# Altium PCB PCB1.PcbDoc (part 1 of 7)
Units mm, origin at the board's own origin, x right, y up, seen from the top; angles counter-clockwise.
Board outline 139.9 x 46.81 mm, 2 copper layers (Top Layer, Bottom Layer); 0 components, 100 nets, 100 pads, 0 vias.
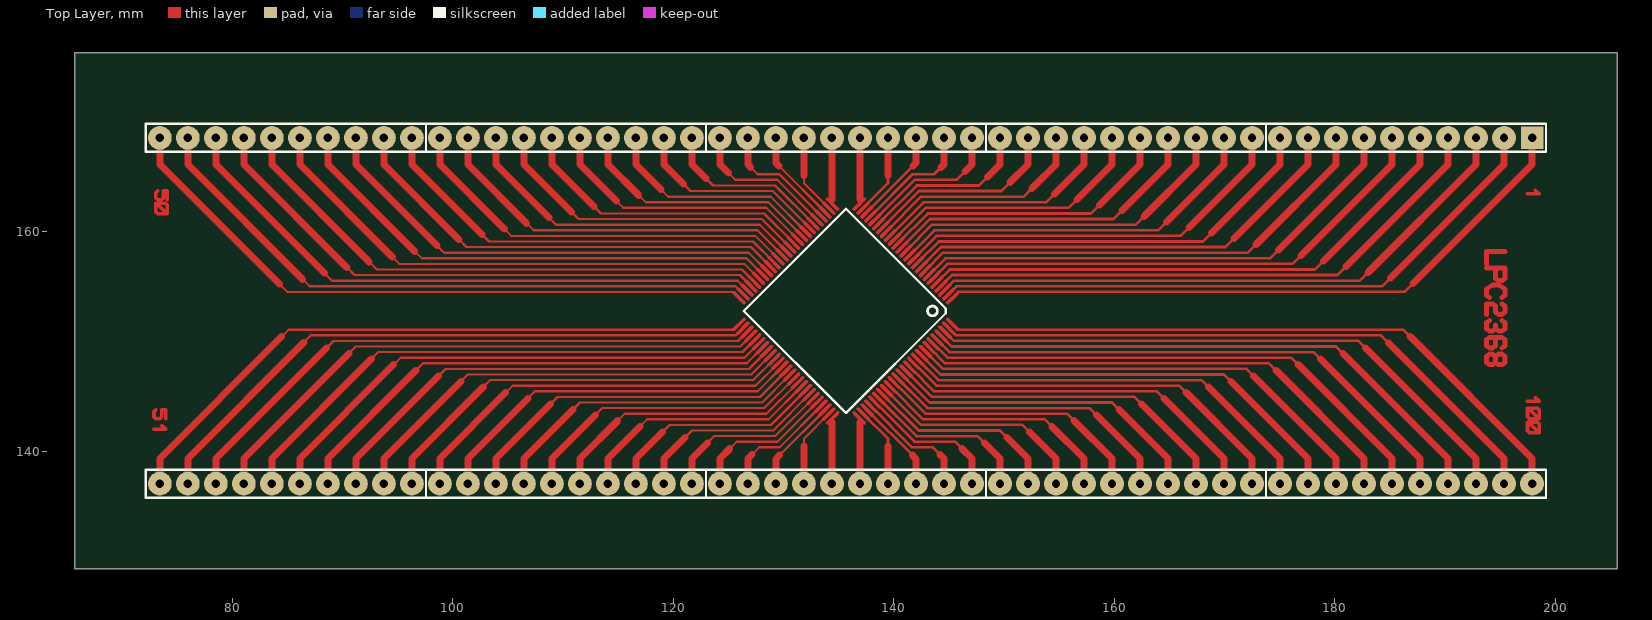
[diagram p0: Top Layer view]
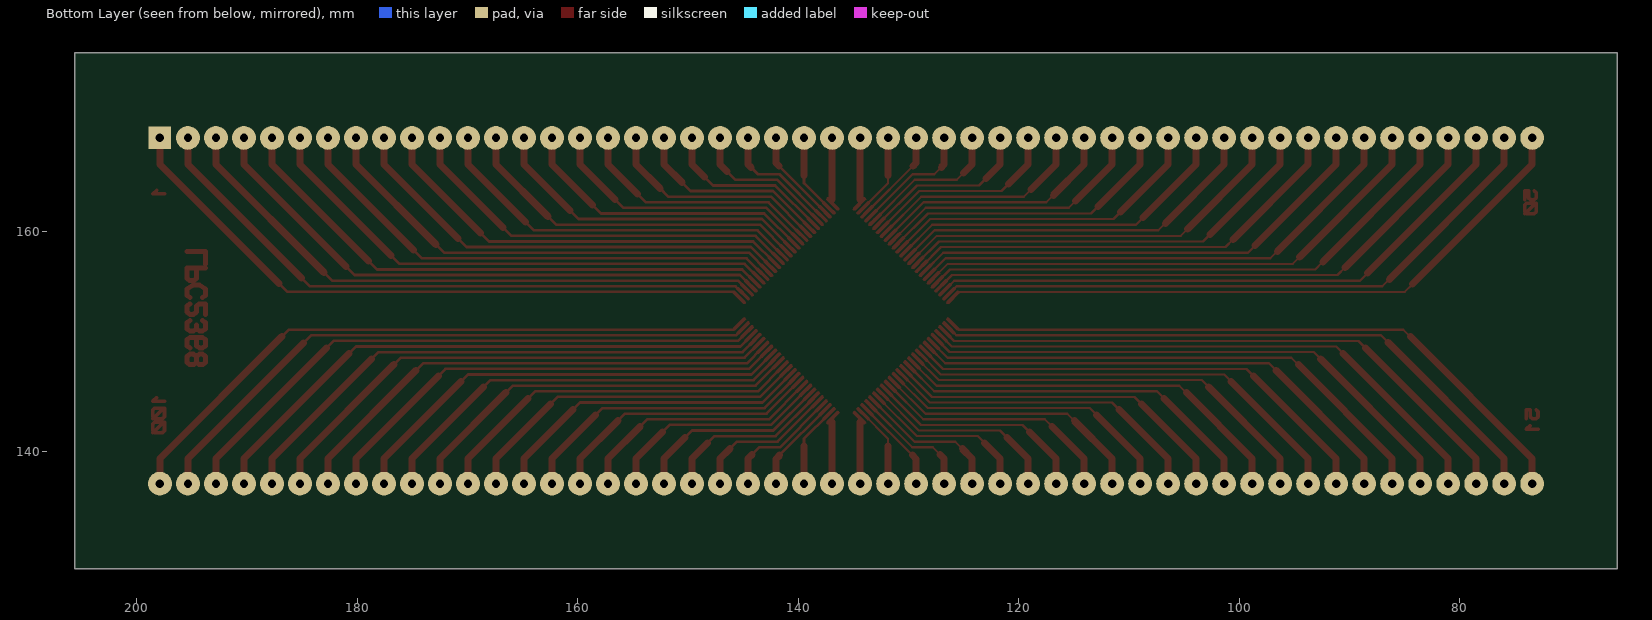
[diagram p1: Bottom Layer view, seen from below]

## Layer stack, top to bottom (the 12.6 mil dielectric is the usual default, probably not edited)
Top Layer: signal copper 0.0356
Dielectric: dielectric 0.32, FR-4, Dk 4.8
Bottom Layer: signal copper 0.0356

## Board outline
65.71,129.362 205.613,129.362 205.613,176.174 65.71,176.174

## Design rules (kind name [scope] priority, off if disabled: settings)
Clearance CAM_Clearance_2 [OnLayer('Top Layer')] p1: gap=0
Clearance CAM_Clearance_1 [OnLayer('Bottom Layer')] p2: gap=0.127
Clearance [All] p3: gap=0.254
PolygonConnect [All] p1: connectstyle=Relief reliefconductorwidth=0.254 reliefentries=4 polygonreliefangle="90 Angle"
RoutingVias [All] p1: holewidth=0.711 width=1.27 viastyle="Through Hole" minholewidth=0.711 minwidth=1.27 maxholewidth=0.711 maxwidth=1.27
SilkscreenOverComponentPads [All] p1: minsilkscreentomaskgap=0.254
SolderMaskExpansion [All] p1: expansion=0.102
Width CAM_Width_1 [OnLayer('Top Layer')] p1: maxlimit=0.66 minlimit=0.005 preferedwidth=0.03
Width [All] p2: maxlimit=0.254 minlimit=0.254 preferedwidth=0.254
27 further rules are at their usual default settings.

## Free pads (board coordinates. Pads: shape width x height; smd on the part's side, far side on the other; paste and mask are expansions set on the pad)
  round 2.159 hole 0.762: 1(73.427,137.086) 1(73.427,168.455) 1(75.967,137.086) 1(75.967,168.455) 1(78.507,137.086) 1(78.507,168.455) 1(81.047,137.086) 1(81.047,168.455) 1(83.587,137.086) 1(83.587,168.455) 1(86.127,137.086) 1(86.127,168.455) 1(88.667,137.086) 1(88.667,168.455) 1(91.207,137.086) 1(91.207,168.455) 1(93.747,137.086) 1(93.747,168.455) 1(96.287,137.086) 1(96.287,168.455) 1(98.827,137.086) 1(98.827,168.455) 1(101.367,137.086) 1(101.367,168.455) 1(103.907,137.086) 1(103.907,168.455) 1(106.447,137.086) 1(106.447,168.455) 1(108.987,137.086) 1(108.987,168.455) 1(111.527,137.086) 1(111.527,168.455) 1(114.067,137.086) 1(114.067,168.455) 1(116.607,137.086) 1(116.607,168.455) 1(119.147,137.086) 1(119.147,168.455) 1(121.687,137.086) 1(121.687,168.455) 1(124.227,137.086) 1(124.227,168.455) 1(126.767,137.086) 1(126.767,168.455) 1(129.307,137.086) 1(129.307,168.455) 1(131.847,137.086) 1(131.847,168.455) 1(134.387,137.086) 1(134.387,168.455) 1(136.927,137.086) 1(136.927,168.455) 1(139.467,137.086) 1(139.467,168.455) 1(142.007,137.086) 1(142.007,168.455) 1(144.547,137.086) 1(144.547,168.455) 1(147.087,137.086) 1(147.087,168.455) 1(149.627,137.086) 1(149.627,168.455) 1(152.167,137.086) 1(152.167,168.455) 1(154.707,137.086) 1(154.707,168.455) 1(157.247,137.086) 1(157.247,168.455) 1(159.787,137.086) 1(159.787,168.455) 1(162.327,137.086) 1(162.327,168.455) 1(164.867,137.086) 1(164.867,168.455) 1(167.407,137.086) 1(167.407,168.455) 1(169.947,137.086) 1(169.947,168.455) 1(172.487,137.086) 1(172.487,168.455) 1(175.025,137.086) 1(175.025,168.455) 1(177.565,137.086) 1(177.565,168.455) 1(180.105,137.086) 1(180.105,168.455) 1(182.645,137.086) 1(182.645,168.455) 1(185.185,137.086) 1(185.185,168.455) 1(187.725,137.086) 1(187.725,168.455) 1(190.265,137.086) 1(190.265,168.455) 1(192.805,137.086) 1(192.805,168.455) 1(195.345,137.086) 1(195.345,168.455) 1(197.885,137.086)
  rect 2.032x2.032 hole 0.762: 1(197.885,168.455)

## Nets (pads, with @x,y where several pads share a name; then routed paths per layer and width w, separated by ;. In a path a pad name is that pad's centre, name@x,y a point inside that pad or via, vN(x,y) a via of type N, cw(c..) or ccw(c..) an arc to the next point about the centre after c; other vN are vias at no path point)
$Net0: pad.1@73.427,168.455 | length 83.9
  Top Layer w0.03: 125.403,154.411 125.672,154.411 ; 125.406,154.396 125.688,154.396 ; 125.408,154.381 125.703,154.381 ; 125.416,154.365 125.718,154.365 ; 125.418,154.457 125.627,154.457 ; 125.429,154.35 125.733,154.35 ; 125.444,154.335 125.749,154.335 ; 125.444,154.487 125.596,154.487 ; 125.459,154.32 125.764,154.32 ; 125.462,154.503 125.581,154.503 ; 125.474,154.304 125.779,154.304 ; 125.484,154.518 125.558,154.518 ; 125.489,154.289 125.794,154.289 ; 125.505,154.274 125.81,154.274 ; 125.52,154.259 125.825,154.259 ; 125.535,154.243 125.84,154.243 ; 125.55,154.228 125.855,154.228 ; 125.566,154.213 125.87,154.213 ; 125.581,154.198 125.886,154.198 ; 125.596,154.182 125.901,154.182 ; 125.611,154.167 125.916,154.167 ; 125.611,154.472 125.429,154.472 ; 125.627,154.152 125.931,154.152 ; 125.642,154.137 125.947,154.137 ; 125.642,154.442 125.408,154.442 ; 125.657,154.122 125.962,154.122 ; 125.657,154.426 125.403,154.426 ; 125.672,154.106 125.977,154.106 ; 125.688,154.091 125.992,154.091 ; 125.703,154.076 126.008,154.076 ; 125.718,154.061 126.023,154.061 ; 125.733,154.045 126.038,154.045 ; 125.749,154.03 126.053,154.03 ; 125.764,154.015 126.066,154.015 ; 125.779,154 126.081,154 ; 125.794,153.984 126.097,153.984 ; 125.81,153.969 126.112,153.969 ; 125.825,153.954 126.127,153.954 ; 125.84,153.939 126.142,153.939 ; 125.855,153.923 126.157,153.923 ; 125.87,153.908 126.173,153.908 ; 125.886,153.893 126.188,153.893 ; 125.898,153.878 126.203,153.878 ; 125.914,153.862 126.218,153.862 ; 125.929,153.847 126.234,153.847 ; 125.944,153.832 126.249,153.832 ; 125.959,153.817 126.264,153.817 ; 125.975,153.801 126.279,153.801 ; 125.99,153.786 126.295,153.786 ; 126.005,153.771 126.31,153.771 ; 126.02,153.756 126.325,153.756 ; 126.036,153.741 126.34,153.741 ; 126.051,153.725 126.356,153.725 ; 126.066,153.71 126.371,153.71 ; 126.081,153.695 126.386,153.695 ; 126.097,153.68 126.401,153.68 ; 126.112,153.664 126.417,153.664 ; 126.127,153.649 126.432,153.649 ; 126.142,153.634 126.447,153.634 ; 126.157,153.619 126.462,153.619 ; 126.173,153.603 126.478,153.603 ; 126.188,153.588 126.493,153.588 ; 126.203,153.573 126.508,153.573 ; 126.218,153.558 126.523,153.558 ; 126.234,153.542 126.531,153.542 ; 126.249,153.527 126.536,153.527 ; 126.264,153.512 126.538,153.512 ; 126.279,153.497 126.538,153.497 ; 126.295,153.481 126.533,153.481 ; 126.31,153.466 126.526,153.466 ; 126.325,153.451 126.516,153.451 ; 126.34,153.436 126.5,153.436 ; 126.356,153.42 126.485,153.42 ; 126.465,153.405 126.371,153.405 ; 125.403,154.426 125.408,154.442 ; 125.403,154.426 125.401,154.409 125.408,154.376 125.416,154.363 126.358,153.415 126.371,153.405 ; 125.408,154.442 125.429,154.472 ; 125.429,154.472 125.456,154.5 125.487,154.52 125.502,154.525 125.52,154.528 125.553,154.52 125.568,154.513 125.581,154.503 ; 125.581,154.503 126.523,153.555 126.531,153.542 ; 126.371,153.405 126.386,153.398 126.419,153.39 126.437,153.393 126.452,153.398 126.483,153.418 126.511,153.446 126.531,153.476 126.536,153.492 126.538,153.509 126.531,153.542
  Top Layer w0.203: 84.286,155.183 84.984,154.485 125.444,154.485 125.97,153.959
  Top Layer w0.635: pad.1@73.427,168.455 73.427,166.042 84.286,155.183
$Net1: pad.1@75.967,168.455 | length 81.5
  Top Layer w0.03: 125.756,154.764 126.025,154.764 ; 125.759,154.749 126.041,154.749 ; 125.761,154.734 126.056,154.734 ; 125.769,154.718 126.071,154.718 ; 125.771,154.81 125.98,154.81 ; 125.782,154.703 126.086,154.703 ; 125.797,154.688 126.102,154.688 ; 125.797,154.84 125.949,154.84 ; 125.812,154.673 126.117,154.673 ; 125.815,154.856 125.934,154.856 ; 125.827,154.657 126.132,154.657 ; 125.837,154.871 125.911,154.871 ; 125.843,154.642 126.147,154.642 ; 125.858,154.627 126.163,154.627 ; 125.873,154.612 126.178,154.612 ; 125.888,154.597 126.193,154.597 ; 125.903,154.581 126.208,154.581 ; 125.919,154.566 126.224,154.566 ; 125.934,154.551 126.239,154.551 ; 125.949,154.536 126.254,154.536 ; 125.964,154.52 126.269,154.52 ; 125.964,154.825 125.782,154.825 ; 125.98,154.505 126.284,154.505 ; 125.995,154.49 126.3,154.49 ; 125.995,154.795 125.761,154.795 ; 126.01,154.475 126.315,154.475 ; 126.01,154.779 125.756,154.779 ; 126.025,154.459 126.33,154.459 ; 126.041,154.444 126.345,154.444 ; 126.056,154.429 126.361,154.429 ; 126.071,154.414 126.376,154.414 ; 126.086,154.398 126.391,154.398 ; 126.102,154.383 126.406,154.383 ; 126.117,154.368 126.419,154.368 ; 126.132,154.353 126.434,154.353 ; 126.147,154.337 126.45,154.337 ; 126.163,154.322 126.465,154.322 ; 126.178,154.307 126.48,154.307 ; 126.193,154.292 126.495,154.292 ; 126.208,154.276 126.511,154.276 ; 126.224,154.261 126.526,154.261 ; 126.239,154.246 126.541,154.246 ; 126.251,154.231 126.556,154.231 ; 126.267,154.216 126.572,154.216 ; 126.282,154.2 126.587,154.2 ; 126.297,154.185 126.602,154.185 ; 126.312,154.17 126.617,154.17 ; 126.328,154.155 126.632,154.155 ; 126.343,154.139 126.648,154.139 ; 126.358,154.124 126.663,154.124 ; 126.373,154.109 126.678,154.109 ; 126.389,154.094 126.693,154.094 ; 126.404,154.078 126.709,154.078 ; 126.419,154.063 126.724,154.063 ; 126.434,154.048 126.739,154.048 ; 126.45,154.033 126.754,154.033 ; 126.465,154.017 126.77,154.017 ; 126.48,154.002 126.785,154.002 ; 126.495,153.987 126.8,153.987 ; 126.511,153.972 126.815,153.972 ; 126.526,153.956 126.831,153.956 ; 126.541,153.941 126.846,153.941 ; 126.556,153.926 126.861,153.926 ; 126.572,153.911 126.876,153.911 ; 126.587,153.895 126.884,153.895 ; 126.602,153.88 126.889,153.88 ; 126.617,153.865 126.892,153.865 ; 126.632,153.85 126.892,153.85 ; 126.648,153.835 126.886,153.835 ; 126.663,153.819 126.879,153.819 ; 126.678,153.804 126.869,153.804 ; 126.693,153.789 126.853,153.789 ; 126.709,153.774 126.838,153.774 ; 126.818,153.758 126.724,153.758 ; 125.756,154.779 125.761,154.795 ; 125.756,154.779 125.754,154.762 125.761,154.729 125.769,154.716 126.711,153.768 126.724,153.758 ; 125.761,154.795 125.782,154.825 ; 125.782,154.825 125.81,154.853 125.84,154.873 125.855,154.878 125.873,154.881 125.906,154.873 125.921,154.866 125.934,154.856 ; 125.934,154.856 126.876,153.908 126.884,153.895 ; 126.724,153.758 126.739,153.751 126.772,153.743 126.79,153.746 126.805,153.751 126.836,153.771 126.864,153.799 126.884,153.829 126.889,153.845 126.892,153.862 126.884,153.895
  Top Layer w0.203: 86.381,155.628 87.016,154.993 125.642,154.993 126.323,154.312
  Top Layer w0.635: pad.1@75.967,168.455 75.967,166.042 86.381,155.628
$Net2: pad.1@78.507,168.455 | length 79.2
  Top Layer w0.03: 126.109,155.117 126.378,155.117 ; 126.112,155.102 126.394,155.102 ; 126.114,155.087 126.409,155.087 ; 126.122,155.071 126.424,155.071 ; 126.124,155.163 126.333,155.163 ; 126.135,155.056 126.439,155.056 ; 126.15,155.041 126.455,155.041 ; 126.15,155.193 126.302,155.193 ; 126.165,155.026 126.47,155.026 ; 126.168,155.209 126.287,155.209 ; 126.18,155.011 126.485,155.011 ; 126.191,155.224 126.264,155.224 ; 126.196,154.995 126.5,154.995 ; 126.211,154.98 126.516,154.98 ; 126.226,154.965 126.531,154.965 ; 126.241,154.95 126.546,154.95 ; 126.257,154.934 126.561,154.934 ; 126.272,154.919 126.577,154.919 ; 126.287,154.904 126.592,154.904 ; 126.302,154.889 126.607,154.889 ; 126.318,154.873 126.622,154.873 ; 126.318,155.178 126.135,155.178 ; 126.333,154.858 126.638,154.858 ; 126.348,154.843 126.653,154.843 ; 126.348,155.148 126.114,155.148 ; 126.363,154.828 126.668,154.828 ; 126.363,155.132 126.109,155.132 ; 126.378,154.812 126.683,154.812 ; 126.394,154.797 126.699,154.797 ; 126.409,154.782 126.714,154.782 ; 126.424,154.767 126.729,154.767 ; 126.439,154.751 126.744,154.751 ; 126.455,154.736 126.759,154.736 ; 126.47,154.721 126.772,154.721 ; 126.485,154.706 126.787,154.706 ; 126.5,154.69 126.803,154.69 ; 126.516,154.675 126.818,154.675 ; 126.531,154.66 126.833,154.66 ; 126.546,154.645 126.848,154.645 ; 126.561,154.63 126.864,154.63 ; 126.577,154.614 126.879,154.614 ; 126.592,154.599 126.894,154.599 ; 126.605,154.584 126.909,154.584 ; 126.62,154.569 126.925,154.569 ; 126.635,154.553 126.94,154.553 ; 126.65,154.538 126.955,154.538 ; 126.665,154.523 126.97,154.523 ; 126.681,154.508 126.986,154.508 ; 126.696,154.492 127.001,154.492 ; 126.711,154.477 127.016,154.477 ; 126.726,154.462 127.031,154.462 ; 126.742,154.447 127.046,154.447 ; 126.757,154.431 127.062,154.431 ; 126.772,154.416 127.077,154.416 ; 126.787,154.401 127.092,154.401 ; 126.803,154.386 127.107,154.386 ; 126.818,154.37 127.123,154.37 ; 126.833,154.355 127.138,154.355 ; 126.848,154.34 127.153,154.34 ; 126.864,154.325 127.168,154.325 ; 126.879,154.309 127.184,154.309 ; 126.894,154.294 127.199,154.294 ; 126.909,154.279 127.214,154.279 ; 126.925,154.264 127.229,154.264 ; 126.94,154.249 127.237,154.249 ; 126.955,154.233 127.242,154.233 ; 126.97,154.218 127.245,154.218 ; 126.986,154.203 127.245,154.203 ; 127.001,154.188 127.24,154.188 ; 127.016,154.172 127.232,154.172 ; 127.031,154.157 127.222,154.157 ; 127.046,154.142 127.207,154.142 ; 127.062,154.127 127.191,154.127 ; 127.171,154.111 127.077,154.111 ; 126.109,155.132 126.114,155.148 ; 126.109,155.132 126.107,155.115 126.114,155.082 126.122,155.069 127.064,154.122 127.077,154.111 ; 126.114,155.148 126.135,155.178 ; 126.135,155.178 126.163,155.206 126.193,155.226 126.208,155.232 126.226,155.234 126.259,155.226 126.274,155.219 126.287,155.209 ; 126.287,155.209 127.229,154.261 127.237,154.249 ; 127.077,154.111 127.092,154.104 127.125,154.096 127.143,154.099 127.158,154.104 127.189,154.124 127.217,154.152 127.237,154.182 127.242,154.198 127.245,154.216 127.237,154.249
  Top Layer w0.203: 88.35,156.199 89.048,155.501 125.843,155.501 126.676,154.665
  Top Layer w0.635: pad.1@78.507,168.455 78.507,166.042 88.35,156.199
$Net3: pad.1@81.047,168.455 | length 76.9
  Top Layer w0.03: 126.462,155.473 126.732,155.473 ; 126.465,155.458 126.747,155.458 ; 126.467,155.442 126.762,155.442 ; 126.475,155.427 126.777,155.427 ; 126.478,155.519 126.686,155.519 ; 126.488,155.412 126.792,155.412 ; 126.503,155.397 126.808,155.397 ; 126.503,155.549 126.655,155.549 ; 126.518,155.381 126.823,155.381 ; 126.521,155.564 126.64,155.564 ; 126.533,155.366 126.838,155.366 ; 126.544,155.579 126.617,155.579 ; 126.549,155.351 126.853,155.351 ; 126.564,155.336 126.869,155.336 ; 126.579,155.32 126.884,155.32 ; 126.594,155.305 126.899,155.305 ; 126.61,155.29 126.914,155.29 ; 126.625,155.275 126.93,155.275 ; 126.64,155.259 126.945,155.259 ; 126.655,155.244 126.96,155.244 ; 126.671,155.229 126.975,155.229 ; 126.671,155.534 126.488,155.534 ; 126.686,155.214 126.991,155.214 ; 126.701,155.198 127.006,155.198 ; 126.701,155.503 126.467,155.503 ; 126.716,155.183 127.021,155.183 ; 126.716,155.488 126.462,155.488 ; 126.732,155.168 127.036,155.168 ; 126.747,155.153 127.052,155.153 ; 126.762,155.138 127.067,155.138 ; 126.777,155.122 127.082,155.122 ; 126.792,155.107 127.097,155.107 ; 126.808,155.092 127.113,155.092 ; 126.823,155.077 127.125,155.077 ; 126.838,155.061 127.14,155.061 ; 126.853,155.046 127.156,155.046 ; 126.869,155.031 127.171,155.031 ; 126.884,155.016 127.186,155.016 ; 126.899,155 127.201,155 ; 126.914,154.985 127.217,154.985 ; 126.93,154.97 127.232,154.97 ; 126.945,154.955 127.247,154.955 ; 126.958,154.939 127.262,154.939 ; 126.973,154.924 127.278,154.924 ; 126.988,154.909 127.293,154.909 ; 127.003,154.894 127.308,154.894 ; 127.019,154.878 127.323,154.878 ; 127.034,154.863 127.339,154.863 ; 127.049,154.848 127.354,154.848 ; 127.064,154.833 127.369,154.833 ; 127.08,154.817 127.384,154.817 ; 127.095,154.802 127.4,154.802 ; 127.11,154.787 127.415,154.787 ; 127.125,154.772 127.43,154.772 ; 127.14,154.757 127.445,154.757 ; 127.156,154.741 127.461,154.741 ; 127.171,154.726 127.476,154.726 ; 127.186,154.711 127.491,154.711 ; 127.201,154.696 127.506,154.696 ; 127.217,154.68 127.521,154.68 ; 127.232,154.665 127.537,154.665 ; 127.247,154.65 127.552,154.65 ; 127.262,154.635 127.567,154.635 ; 127.278,154.619 127.582,154.619 ; 127.293,154.604 127.59,154.604 ; 127.308,154.589 127.595,154.589 ; 127.323,154.574 127.598,154.574 ; 127.339,154.558 127.598,154.558 ; 127.354,154.543 127.593,154.543 ; 127.369,154.528 127.585,154.528 ; 127.384,154.513 127.575,154.513 ; 127.4,154.497 127.56,154.497 ; 127.415,154.482 127.544,154.482 ; 127.524,154.467 127.43,154.467 ; 126.462,155.488 126.467,155.503 ; 126.462,155.488 126.46,155.47 126.467,155.437 126.475,155.425 127.417,154.477 127.43,154.467 ; 126.467,155.503 126.488,155.534 ; 126.488,155.534 126.516,155.562 126.546,155.582 126.561,155.587 126.579,155.59 126.612,155.582 126.627,155.574 126.64,155.564 ; 126.64,155.564 127.582,154.617 127.59,154.604 ; 127.43,154.467 127.445,154.459 127.478,154.452 127.496,154.454 127.511,154.459 127.542,154.48 127.57,154.508 127.59,154.538 127.595,154.553 127.598,154.571 127.59,154.604
  Top Layer w0.203: 90.382,156.707 91.08,156.009 126.041,156.009 127.029,155.021
  Top Layer w0.635: pad.1@81.047,168.455 81.047,166.042 90.382,156.707
$Net4: pad.1@83.587,168.455 | length 74.5
  Top Layer w0.03: 126.815,155.826 127.085,155.826 ; 126.818,155.811 127.1,155.811 ; 126.82,155.795 127.115,155.795 ; 126.828,155.78 127.13,155.78 ; 126.831,155.872 127.039,155.872 ; 126.841,155.765 127.146,155.765 ; 126.856,155.75 127.161,155.75 ; 126.856,155.902 127.008,155.902 ; 126.871,155.734 127.176,155.734 ; 126.874,155.917 126.993,155.917 ; 126.886,155.719 127.191,155.719 ; 126.897,155.933 126.97,155.933 ; 126.902,155.704 127.207,155.704 ; 126.917,155.689 127.222,155.689 ; 126.932,155.673 127.237,155.673 ; 126.947,155.658 127.252,155.658 ; 126.963,155.643 127.267,155.643 ; 126.978,155.628 127.283,155.628 ; 126.993,155.613 127.298,155.613 ; 127.008,155.597 127.313,155.597 ; 127.024,155.582 127.328,155.582 ; 127.024,155.887 126.841,155.887 ; 127.039,155.567 127.344,155.567 ; 127.054,155.552 127.359,155.552 ; 127.054,155.856 126.82,155.856 ; 127.069,155.536 127.374,155.536 ; 127.069,155.841 126.815,155.841 ; 127.085,155.521 127.389,155.521 ; 127.1,155.506 127.405,155.506 ; 127.115,155.491 127.42,155.491 ; 127.13,155.475 127.435,155.475 ; 127.146,155.46 127.45,155.46 ; 127.161,155.445 127.466,155.445 ; 127.176,155.43 127.478,155.43 ; 127.191,155.414 127.494,155.414 ; 127.207,155.399 127.509,155.399 ; 127.222,155.384 127.524,155.384 ; 127.237,155.369 127.539,155.369 ; 127.252,155.353 127.554,155.353 ; 127.267,155.338 127.57,155.338 ; 127.283,155.323 127.585,155.323 ; 127.298,155.308 127.6,155.308 ; 127.311,155.292 127.615,155.292 ; 127.326,155.277 127.631,155.277 ; 127.341,155.262 127.646,155.262 ; 127.356,155.247 127.661,155.247 ; 127.372,155.232 127.676,155.232 ; 127.387,155.216 127.692,155.216 ; 127.402,155.201 127.707,155.201 ; 127.417,155.186 127.722,155.186 ; 127.433,155.171 127.737,155.171 ; 127.448,155.155 127.753,155.155 ; 127.463,155.14 127.768,155.14 ; 127.478,155.125 127.783,155.125 ; 127.494,155.11 127.798,155.11 ; 127.509,155.094 127.814,155.094 ; 127.524,155.079 127.829,155.079 ; 127.539,155.064 127.844,155.064 ; 127.554,155.049 127.859,155.049 ; 127.57,155.033 127.875,155.033 ; 127.585,155.018 127.89,155.018 ; 127.6,155.003 127.905,155.003 ; 127.615,154.988 127.92,154.988 ; 127.631,154.972 127.935,154.972 ; 127.646,154.957 127.943,154.957 ; 127.661,154.942 127.948,154.942 ; 127.676,154.927 127.951,154.927 ; 127.692,154.911 127.951,154.911 ; 127.707,154.896 127.946,154.896 ; 127.722,154.881 127.938,154.881 ; 127.737,154.866 127.928,154.866 ; 127.753,154.851 127.913,154.851 ; 127.768,154.835 127.897,154.835 ; 127.877,154.82 127.783,154.82 ; 126.815,155.841 126.82,155.856 ; 126.815,155.841 126.813,155.823 126.82,155.79 126.828,155.778 127.77,154.83 127.783,154.82 ; 126.82,155.856 126.841,155.887 ; 126.841,155.887 126.869,155.915 126.899,155.935 126.914,155.94 126.932,155.943 126.965,155.935 126.98,155.927 126.993,155.917 ; 126.993,155.917 127.935,154.97 127.943,154.957 ; 127.783,154.82 127.798,154.812 127.831,154.805 127.849,154.807 127.864,154.812 127.895,154.833 127.923,154.861 127.943,154.891 127.948,154.906 127.951,154.924 127.943,154.957
  Top Layer w0.203: 92.414,157.215 93.112,156.517 126.239,156.517 127.382,155.374
  Top Layer w0.635: pad.1@83.587,168.455 83.587,166.042 92.414,157.215
$Net5: pad.1@86.127,168.455 | length 72.2
  Top Layer w0.03: 127.171,156.179 127.44,156.179 ; 127.173,156.164 127.455,156.164 ; 127.176,156.148 127.471,156.148 ; 127.184,156.133 127.486,156.133 ; 127.186,156.225 127.394,156.225 ; 127.196,156.118 127.501,156.118 ; 127.212,156.103 127.516,156.103 ; 127.212,156.255 127.364,156.255 ; 127.227,156.087 127.532,156.087 ; 127.229,156.27 127.349,156.27 ; 127.242,156.072 127.547,156.072 ; 127.252,156.286 127.326,156.286 ; 127.257,156.057 127.562,156.057 ; 127.273,156.042 127.577,156.042 ; 127.288,156.027 127.593,156.027 ; 127.303,156.011 127.608,156.011 ; 127.318,155.996 127.623,155.996 ; 127.334,155.981 127.638,155.981 ; 127.349,155.966 127.654,155.966 ; 127.364,155.95 127.669,155.95 ; 127.379,155.935 127.684,155.935 ; 127.379,156.24 127.196,156.24 ; 127.394,155.92 127.699,155.92 ; 127.41,155.905 127.715,155.905 ; 127.41,156.209 127.176,156.209 ; 127.425,155.889 127.73,155.889 ; 127.425,156.194 127.171,156.194 ; 127.44,155.874 127.745,155.874 ; 127.455,155.859 127.76,155.859 ; 127.471,155.844 127.775,155.844 ; 127.486,155.828 127.791,155.828 ; 127.501,155.813 127.806,155.813 ; 127.516,155.798 127.821,155.798 ; 127.532,155.783 127.834,155.783 ; 127.547,155.767 127.849,155.767 ; 127.562,155.752 127.864,155.752 ; 127.577,155.737 127.88,155.737 ; 127.593,155.722 127.895,155.722 ; 127.608,155.706 127.91,155.706 ; 127.623,155.691 127.925,155.691 ; 127.638,155.676 127.941,155.676 ; 127.654,155.661 127.956,155.661 ; 127.666,155.646 127.971,155.646 ; 127.681,155.63 127.986,155.63 ; 127.697,155.615 128.002,155.615 ; 127.712,155.6 128.017,155.6 ; 127.727,155.585 128.032,155.585 ; 127.742,155.569 128.047,155.569 ; 127.758,155.554 128.062,155.554 ; 127.773,155.539 128.078,155.539 ; 127.788,155.524 128.093,155.524 ; 127.803,155.508 128.108,155.508 ; 127.819,155.493 128.123,155.493 ; 127.834,155.478 128.139,155.478 ; 127.849,155.463 128.154,155.463 ; 127.864,155.447 128.169,155.447 ; 127.88,155.432 128.184,155.432 ; 127.895,155.417 128.2,155.417 ; 127.91,155.402 128.215,155.402 ; 127.925,155.386 128.23,155.386 ; 127.941,155.371 128.245,155.371 ; 127.956,155.356 128.261,155.356 ; 127.971,155.341 128.276,155.341 ; 127.986,155.325 128.291,155.325 ; 128.002,155.31 128.299,155.31 ; 128.017,155.295 128.304,155.295 ; 128.032,155.28 128.306,155.28 ; 128.047,155.265 128.306,155.265 ; 128.062,155.249 128.301,155.249 ; 128.078,155.234 128.294,155.234 ; 128.093,155.219 128.283,155.219 ; 128.108,155.204 128.268,155.204 ; 128.123,155.188 128.253,155.188 ; 128.233,155.173 128.139,155.173 ; 127.171,156.194 127.176,156.209 ; 127.171,156.194 127.168,156.176 127.176,156.143 127.184,156.131 128.126,155.183 128.139,155.173 ; 127.176,156.209 127.196,156.24 ; 127.196,156.24 127.224,156.268 127.255,156.288 127.27,156.293 127.288,156.296 127.321,156.288 127.336,156.281 127.349,156.27 ; 127.349,156.27 128.291,155.323 128.299,155.31 ; 128.139,155.173 128.154,155.165 128.187,155.158 128.205,155.16 128.22,155.165 128.25,155.186 128.278,155.214 128.299,155.244 128.304,155.259 128.306,155.277 128.299,155.31
  Top Layer w0.203: 94.509,157.66 95.144,157.025 126.439,157.025 127.737,155.727
  Top Layer w0.635: pad.1@86.127,168.455 86.127,166.042 94.509,157.66
$Net6: pad.1@88.667,168.455 | length 69.9
  Top Layer w0.03: 127.524,156.532 127.793,156.532 ; 127.527,156.517 127.808,156.517 ; 127.529,156.502 127.824,156.502 ; 127.537,156.486 127.839,156.486 ; 127.539,156.578 127.748,156.578 ; 127.549,156.471 127.854,156.471 ; 127.565,156.456 127.869,156.456 ; 127.565,156.608 127.717,156.608 ; 127.58,156.441 127.885,156.441 ; 127.582,156.623 127.702,156.623 ; 127.595,156.425 127.9,156.425 ; 127.605,156.639 127.679,156.639 ; 127.61,156.41 127.915,156.41 ; 127.626,156.395 127.93,156.395 ; 127.641,156.38 127.946,156.38 ; 127.656,156.364 127.961,156.364 ; 127.671,156.349 127.976,156.349 ; 127.687,156.334 127.991,156.334 ; 127.702,156.319 128.007,156.319 ; 127.717,156.303 128.022,156.303 ; 127.732,156.288 128.037,156.288 ; 127.732,156.593 127.549,156.593 ; 127.748,156.273 128.052,156.273 ; 127.763,156.258 128.068,156.258 ; 127.763,156.562 127.529,156.562 ; 127.778,156.242 128.083,156.242 ; 127.778,156.547 127.524,156.547 ; 127.793,156.227 128.098,156.227 ; 127.808,156.212 128.113,156.212 ; 127.824,156.197 128.129,156.197 ; 127.839,156.181 128.144,156.181 ; 127.854,156.166 128.159,156.166 ; 127.869,156.151 128.174,156.151 ; 127.885,156.136 128.187,156.136 ; 127.9,156.121 128.202,156.121 ; 127.915,156.105 128.217,156.105 ; 127.93,156.09 128.233,156.09 ; 127.946,156.075 128.248,156.075 ; 127.961,156.06 128.263,156.06 ; 127.976,156.044 128.278,156.044 ; 127.991,156.029 128.294,156.029 ; 128.007,156.014 128.309,156.014 ; 128.019,155.999 128.324,155.999 ; 128.035,155.983 128.339,155.983 ; 128.05,155.968 128.355,155.968 ; 128.065,155.953 128.37,155.953 ; 128.08,155.938 128.385,155.938 ; 128.096,155.922 128.4,155.922 ; 128.111,155.907 128.416,155.907 ; 128.126,155.892 128.431,155.892 ; 128.141,155.877 128.446,155.877 ; 128.156,155.861 128.461,155.861 ; 128.172,155.846 128.477,155.846 ; 128.187,155.831 128.492,155.831 ; 128.202,155.816 128.507,155.816 ; 128.217,155.8 128.522,155.8 ; 128.233,155.785 128.537,155.785 ; 128.248,155.77 128.553,155.77 ; 128.263,155.755 128.568,155.755 ; 128.278,155.74 128.583,155.74 ; 128.294,155.724 128.598,155.724 ; 128.309,155.709 128.614,155.709 ; 128.324,155.694 128.629,155.694 ; 128.339,155.679 128.644,155.679 ; 128.355,155.663 128.652,155.663 ; 128.37,155.648 128.657,155.648 ; 128.385,155.633 128.659,155.633 ; 128.4,155.618 128.659,155.618 ; 128.416,155.602 128.654,155.602 ; 128.431,155.587 128.647,155.587 ; 128.446,155.572 128.637,155.572 ; 128.461,155.557 128.621,155.557 ; 128.477,155.541 128.606,155.541 ; 128.586,155.526 128.492,155.526 ; 127.524,156.547 127.529,156.562 ; 127.524,156.547 127.521,156.529 127.529,156.496 127.537,156.484 128.479,155.536 128.492,155.526 ; 127.529,156.562 127.549,156.593 ; 127.549,156.593 127.577,156.621 127.608,156.641 127.623,156.646 127.641,156.649 127.674,156.641 127.689,156.634 127.702,156.623 ; 127.702,156.623 128.644,155.676 128.652,155.663 ; 128.492,155.526 128.507,155.519 128.54,155.511 128.558,155.513 128.573,155.519 128.604,155.539 128.631,155.567 128.652,155.597 128.657,155.613 128.659,155.63 128.652,155.663
  Top Layer w0.203: 96.541,158.168 97.176,157.533 126.638,157.533 128.09,156.08
  Top Layer w0.635: pad.1@88.667,168.455 88.667,166.042 96.541,158.168
$Net7: pad.1@91.207,168.455 | length 67.5
  Top Layer w0.03: 127.877,156.885 128.146,156.885 ; 127.88,156.87 128.162,156.87 ; 127.882,156.855 128.177,156.855 ; 127.89,156.839 128.192,156.839 ; 127.892,156.931 128.101,156.931 ; 127.902,156.824 128.207,156.824 ; 127.918,156.809 128.223,156.809 ; 127.918,156.961 128.07,156.961 ; 127.933,156.794 128.238,156.794 ; 127.935,156.976 128.055,156.976 ; 127.948,156.778 128.253,156.778 ; 127.958,156.992 128.032,156.992 ; 127.963,156.763 128.268,156.763 ; 127.979,156.748 128.283,156.748 ; 127.994,156.733 128.299,156.733 ; 128.009,156.717 128.314,156.717 ; 128.024,156.702 128.329,156.702 ; 128.04,156.687 128.344,156.687 ; 128.055,156.672 128.36,156.672 ; 128.07,156.656 128.375,156.656 ; 128.085,156.641 128.39,156.641 ; 128.085,156.946 127.902,156.946 ; 128.101,156.626 128.405,156.626 ; 128.116,156.611 128.421,156.611 ; 128.116,156.916 127.882,156.916 ; 128.131,156.595 128.436,156.595 ; 128.131,156.9 127.877,156.9 ; 128.146,156.58 128.451,156.58 ; 128.162,156.565 128.466,156.565 ; 128.177,156.55 128.482,156.55 ; 128.192,156.535 128.497,156.535 ; 128.207,156.519 128.512,156.519 ; 128.223,156.504 128.527,156.504 ; 128.238,156.489 128.54,156.489 ; 128.253,156.474 128.555,156.474 ; 128.268,156.458 128.57,156.458 ; 128.283,156.443 128.586,156.443 ; 128.299,156.428 128.601,156.428 ; 128.314,156.413 128.616,156.413 ; 128.329,156.397 128.631,156.397 ; 128.344,156.382 128.647,156.382 ; 128.36,156.367 128.662,156.367 ; 128.372,156.352 128.677,156.352 ; 128.388,156.336 128.692,156.336 ; 128.403,156.321 128.708,156.321 ; 128.418,156.306 128.723,156.306 ; 128.433,156.291 128.738,156.291 ; 128.449,156.275 128.753,156.275 ; 128.464,156.26 128.769,156.26 ; 128.479,156.245 128.784,156.245 ; 128.494,156.23 128.799,156.23 ; 128.51,156.214 128.814,156.214 ; 128.525,156.199 128.83,156.199 ; 128.54,156.184 128.845,156.184 ; 128.555,156.169 128.86,156.169 ; 128.57,156.154 128.875,156.154 ; 128.586,156.138 128.891,156.138 ; 128.601,156.123 128.906,156.123 ; 128.616,156.108 128.921,156.108 ; 128.631,156.093 128.936,156.093 ; 128.647,156.077 128.951,156.077 ; 128.662,156.062 128.967,156.062 ; 128.677,156.047 128.982,156.047 ; 128.692,156.032 128.997,156.032 ; 128.708,156.016 129.005,156.016 ; 128.723,156.001 129.01,156.001 ; 128.738,155.986 129.012,155.986 ; 128.753,155.971 129.012,155.971 ; 128.769,155.955 129.007,155.955 ; 128.784,155.94 129,155.94 ; 128.799,155.925 128.99,155.925 ; 128.814,155.91 128.974,155.91 ; 128.83,155.894 128.959,155.894 ; 128.939,155.879 128.845,155.879 ; 127.877,156.9 127.882,156.916 ; 127.877,156.9 127.875,156.883 127.882,156.849 127.89,156.837 128.832,155.889 128.845,155.879 ; 127.882,156.916 127.902,156.946 ; 127.902,156.946 127.93,156.974 127.961,156.994 127.976,156.999 127.994,157.002 128.027,156.994 128.042,156.987 128.055,156.976 ; 128.055,156.976 128.997,156.029 129.005,156.016 ; 128.845,155.879 128.86,155.872 128.893,155.864 128.911,155.867 128.926,155.872 128.957,155.892 128.985,155.92 129.005,155.95 129.01,155.966 129.012,155.983 129.005,156.016
  Top Layer w0.203: 98.573,158.676 99.208,158.041 126.838,158.041 128.443,156.433
  Top Layer w0.635: pad.1@91.207,168.455 91.207,166.042 98.573,158.676
$Net8: pad.1@93.747,168.455 | length 65.2
  Top Layer w0.03: 128.23,157.241 128.499,157.241 ; 128.233,157.225 128.515,157.225 ; 128.235,157.21 128.53,157.21 ; 128.243,157.195 128.545,157.195 ; 128.245,157.286 128.454,157.286 ; 128.256,157.18 128.56,157.18 ; 128.271,157.164 128.576,157.164 ; 128.271,157.317 128.423,157.317 ; 128.286,157.149 128.591,157.149 ; 128.289,157.332 128.408,157.332 ; 128.301,157.134 128.606,157.134 ; 128.311,157.347 128.385,157.347 ; 128.316,157.119 128.621,157.119 ; 128.332,157.103 128.637,157.103 ; 128.347,157.088 128.652,157.088 ; 128.362,157.073 128.667,157.073 ; 128.377,157.058 128.682,157.058 ; 128.393,157.043 128.697,157.043 ; 128.408,157.027 128.713,157.027 ; 128.423,157.012 128.728,157.012 ; 128.438,156.997 128.743,156.997 ; 128.438,157.302 128.256,157.302 ; 128.454,156.982 128.758,156.982 ; 128.469,156.966 128.774,156.966 ; 128.469,157.271 128.235,157.271 ; 128.484,156.951 128.789,156.951 ; 128.484,157.256 128.23,157.256 ; 128.499,156.936 128.804,156.936 ; 128.515,156.921 128.819,156.921 ; 128.53,156.905 128.835,156.905 ; 128.545,156.89 128.85,156.89 ; 128.56,156.875 128.865,156.875 ; 128.576,156.86 128.88,156.86 ; 128.591,156.844 128.893,156.844 ; 128.606,156.829 128.908,156.829 ; 128.621,156.814 128.924,156.814 ; 128.637,156.799 128.939,156.799 ; 128.652,156.783 128.954,156.783 ; 128.667,156.768 128.969,156.768 ; 128.682,156.753 128.985,156.753 ; 128.697,156.738 129,156.738 ; 128.713,156.722 129.015,156.722 ; 128.725,156.707 129.03,156.707 ; 128.741,156.692 129.045,156.692 ; 128.756,156.677 129.061,156.677 ; 128.771,156.662 129.076,156.662 ; 128.786,156.646 129.091,156.646 ; 128.802,156.631 129.106,156.631 ; 128.817,156.616 129.122,156.616 ; 128.832,156.601 129.137,156.601 ; 128.847,156.585 129.152,156.585 ; 128.863,156.57 129.167,156.57 ; 128.878,156.555 129.183,156.555 ; 128.893,156.54 129.198,156.54 ; 128.908,156.524 129.213,156.524 ; 128.924,156.509 129.228,156.509 ; 128.939,156.494 129.244,156.494 ; 128.954,156.479 129.259,156.479 ; 128.969,156.463 129.274,156.463 ; 128.985,156.448 129.289,156.448 ; 129,156.433 129.305,156.433 ; 129.015,156.418 129.32,156.418 ; 129.03,156.402 129.335,156.402 ; 129.045,156.387 129.35,156.387 ; 129.061,156.372 129.358,156.372 ; 129.076,156.357 129.363,156.357 ; 129.091,156.341 129.366,156.341 ; 129.106,156.326 129.366,156.326 ; 129.122,156.311 129.36,156.311 ; 129.137,156.296 129.353,156.296 ; 129.152,156.281 129.343,156.281 ; 129.167,156.265 129.327,156.265 ; 129.183,156.25 129.312,156.25 ; 129.292,156.235 129.198,156.235 ; 128.23,157.256 128.235,157.271 ; 128.23,157.256 128.228,157.238 128.235,157.205 128.243,157.192 129.185,156.245 129.198,156.235 ; 128.235,157.271 128.256,157.302 ; 128.256,157.302 128.283,157.33 128.314,157.35 128.329,157.355 128.347,157.357 128.38,157.35 128.395,157.342 128.408,157.332 ; 128.408,157.332 129.35,156.385 129.358,156.372 ; 129.198,156.235 129.213,156.227 129.246,156.22 129.264,156.222 129.279,156.227 129.31,156.248 129.338,156.275 129.358,156.306 129.363,156.321 129.366,156.339 129.358,156.372
  Top Layer w0.203: 100.542,159.247 101.24,158.549 127.036,158.549 128.797,156.789
  Top Layer w0.635: pad.1@93.747,168.455 93.747,166.042 100.542,159.247
$Net9: pad.1@96.287,168.455 | length 62.9
  Top Layer w0.03: 128.583,157.594 128.852,157.594 ; 128.586,157.578 128.868,157.578 ; 128.588,157.563 128.883,157.563 ; 128.596,157.548 128.898,157.548 ; 128.598,157.639 128.807,157.639 ; 128.609,157.533 128.913,157.533 ; 128.624,157.518 128.929,157.518 ; 128.624,157.67 128.776,157.67 ; 128.639,157.502 128.944,157.502 ; 128.642,157.685 128.761,157.685 ; 128.654,157.487 128.959,157.487 ; 128.664,157.7 128.738,157.7 ; 128.67,157.472 128.974,157.472 ; 128.685,157.457 128.99,157.457 ; 128.7,157.441 129.005,157.441 ; 128.715,157.426 129.02,157.426 ; 128.731,157.411 129.035,157.411 ; 128.746,157.396 129.051,157.396 ; 128.761,157.38 129.066,157.38 ; 128.776,157.365 129.081,157.365 ; 128.791,157.35 129.096,157.35 ; 128.791,157.655 128.609,157.655 ; 128.807,157.335 129.112,157.335 ; 128.822,157.319 129.127,157.319 ; 128.822,157.624 128.588,157.624 ; 128.837,157.304 129.142,157.304 ; 128.837,157.609 128.583,157.609 ; 128.852,157.289 129.157,157.289 ; 128.868,157.274 129.172,157.274 ; 128.883,157.258 129.188,157.258 ; 128.898,157.243 129.203,157.243 ; 128.913,157.228 129.218,157.228 ; 128.929,157.213 129.233,157.213 ; 128.944,157.197 129.246,157.197 ; 128.959,157.182 129.261,157.182 ; 128.974,157.167 129.277,157.167 ; 128.99,157.152 129.292,157.152 ; 129.005,157.137 129.307,157.137 ; 129.02,157.121 129.322,157.121 ; 129.035,157.106 129.338,157.106 ; 129.051,157.091 129.353,157.091 ; 129.066,157.076 129.368,157.076 ; 129.078,157.06 129.383,157.06 ; 129.094,157.045 129.399,157.045 ; 129.109,157.03 129.414,157.03 ; 129.124,157.015 129.429,157.015 ; 129.139,156.999 129.444,156.999 ; 129.155,156.984 129.459,156.984 ; 129.17,156.969 129.475,156.969 ; 129.185,156.954 129.49,156.954 ; 129.2,156.938 129.505,156.938 ; 129.216,156.923 129.52,156.923 ; 129.231,156.908 129.536,156.908 ; 129.246,156.893 129.551,156.893 ; 129.261,156.877 129.566,156.877 ; 129.277,156.862 129.581,156.862 ; 129.292,156.847 129.597,156.847 ; 129.307,156.832 129.612,156.832 ; 129.322,156.816 129.627,156.816 ; 129.338,156.801 129.642,156.801 ; 129.353,156.786 129.658,156.786 ; 129.368,156.771 129.673,156.771 ; 129.383,156.756 129.688,156.756 ; 129.399,156.74 129.703,156.74 ; 129.414,156.725 129.711,156.725 ; 129.429,156.71 129.716,156.71 ; 129.444,156.695 129.719,156.695 ; 129.459,156.679 129.719,156.679 ; 129.475,156.664 129.713,156.664 ; 129.49,156.649 129.706,156.649 ; 129.505,156.634 129.696,156.634 ; 129.52,156.618 129.68,156.618 ; 129.536,156.603 129.665,156.603 ; 129.645,156.588 129.551,156.588 ; 128.583,157.609 128.588,157.624 ; 128.583,157.609 128.581,157.591 128.588,157.558 128.596,157.545 129.538,156.598 129.551,156.588 ; 128.588,157.624 128.609,157.655 ; 128.609,157.655 128.637,157.683 128.667,157.703 128.682,157.708 128.7,157.711 128.733,157.703 128.748,157.695 128.761,157.685 ; 128.761,157.685 129.703,156.738 129.711,156.725 ; 129.551,156.588 129.566,156.58 129.599,156.573 129.617,156.575 129.632,156.58 129.663,156.601 129.691,156.629 129.711,156.659 129.716,156.674 129.719,156.692 129.711,156.725
  Top Layer w0.203: 102.637,159.692 103.272,159.057 127.234,159.057 129.15,157.142
  Top Layer w0.635: pad.1@96.287,168.455 96.287,166.042 102.637,159.692
$Net10: pad.1@73.427,137.086 | length 83.8
  Top Layer w0.03: 125.403,151.091 125.66,151.091 ; 125.403,151.107 125.675,151.107 ; 125.406,151.122 125.69,151.122 ; 125.408,151.076 125.644,151.076 ; 125.416,151.061 125.629,151.061 ; 125.426,151.046 125.614,151.046 ; 125.431,151.168 125.736,151.168 ; 125.439,151.03 125.599,151.03 ; 125.446,151.183 125.751,151.183 ; 125.454,151.015 125.583,151.015 ; 125.462,151.198 125.766,151.198 ; 125.477,151 125.566,151 ; 125.477,151.213 125.782,151.213 ; 125.492,151.228 125.797,151.228 ; 125.507,151.244 125.812,151.244 ; 125.522,151.259 125.827,151.259 ; 125.538,151.274 125.843,151.274 ; 125.553,151.289 125.858,151.289 ; 125.568,151.305 125.873,151.305 ; 125.583,151.32 125.888,151.32 ; 125.599,151.335 125.903,151.335 ; 125.614,151.35 125.919,151.35 ; 125.629,151.366 125.934,151.366 ; 125.644,151.381 125.949,151.381 ; 125.66,151.396 125.964,151.396 ; 125.675,151.411 125.98,151.411 ; 125.69,151.427 125.995,151.427 ; 125.705,151.137 125.408,151.137 ; 125.705,151.442 126.01,151.442 ; 125.721,151.152 125.416,151.152 ; 125.721,151.457 126.025,151.457 ; 125.736,151.472 126.043,151.472 ; 125.751,151.488 126.058,151.488 ; 125.766,151.503 126.074,151.503 ; 125.782,151.518 126.089,151.518 ; 125.797,151.533 126.104,151.533 ; 125.812,151.549 126.119,151.549 ; 125.827,151.564 126.135,151.564 ; 125.843,151.579 126.15,151.579 ; 125.858,151.594 126.165,151.594 ; 125.873,151.609 126.18,151.609 ; 125.888,151.625 126.196,151.625 ; 125.906,151.64 126.211,151.64 ; 125.921,151.655 126.226,151.655 ; 125.937,151.67 126.241,151.67 ; 125.952,151.686 126.257,151.686 ; 125.967,151.701 126.272,151.701 ; 125.982,151.716 126.287,151.716 ; 125.997,151.731 126.302,151.731 ; 126.013,151.747 126.318,151.747 ; 126.028,151.762 126.333,151.762 ; 126.043,151.777 126.348,151.777 ; 126.058,151.792 126.363,151.792 ; 126.074,151.808 126.378,151.808 ; 126.089,151.823 126.394,151.823 ; 126.104,151.838 126.409,151.838 ; 126.119,151.853 126.424,151.853 ; 126.135,151.869 126.439,151.869 ; 126.15,151.884 126.455,151.884 ; 126.165,151.899 126.47,151.899 ; 126.18,151.914 126.485,151.914 ; 126.196,151.93 126.5,151.93 ; 126.211,151.945 126.516,151.945 ; 126.226,151.96 126.526,151.96 ; 126.241,151.975 126.533,151.975 ; 126.257,151.99 126.536,151.99 ; 126.272,152.006 126.538,152.006 ; 126.287,152.021 126.536,152.021 ; 126.302,152.036 126.531,152.036 ; 126.318,152.051 126.521,152.051 ; 126.333,152.067 126.511,152.067 ; 126.348,152.082 126.495,152.082 ; 126.363,152.097 126.48,152.097 ; 126.384,152.112 126.457,152.112 ; 125.408,151.137 125.416,151.152 ; 125.408,151.137 125.401,151.104 125.403,151.086 125.408,151.071 125.429,151.041 125.456,151.013 125.487,150.992 125.502,150.987 125.52,150.985 125.553,150.992 125.566,151 ; 125.416,151.152 125.426,151.165 126.373,152.107 126.386,152.115 126.419,152.123 126.437,152.12 126.452,152.115 126.483,152.095 126.511,152.067 ; 125.566,151 126.513,151.942 126.523,151.955 126.531,151.97 126.538,152.003 126.536,152.021 ; 126.511,152.067 126.531,152.036 ; 126.531,152.036 126.536,152.021
  Top Layer w0.203: 84.476,150.421 85.111,151.056 125.469,151.056 125.97,151.554
  Top Layer w0.635: pad.1@73.427,137.086 73.427,139.372 84.476,150.421
$Net11: pad.1@75.967,137.086 | length 81.4
  Top Layer w0.03: 125.756,150.738 126.013,150.738 ; 125.756,150.753 126.028,150.753 ; 125.759,150.769 126.043,150.769 ; 125.761,150.723 125.997,150.723 ; 125.769,150.708 125.982,150.708 ; 125.779,150.693 125.967,150.693 ; 125.784,150.814 126.089,150.814 ; 125.792,150.677 125.952,150.677 ; 125.799,150.83 126.104,150.83 ; 125.807,150.662 125.937,150.662 ; 125.815,150.845 126.119,150.845 ; 125.83,150.647 125.919,150.647 ; 125.83,150.86 126.135,150.86 ; 125.845,150.875 126.15,150.875 ; 125.86,150.891 126.165,150.891 ; 125.876,150.906 126.18,150.906 ; 125.891,150.921 126.196,150.921 ; 125.906,150.936 126.211,150.936 ; 125.921,150.952 126.226,150.952 ; 125.937,150.967 126.241,150.967 ; 125.952,150.982 126.257,150.982 ; 125.967,150.997 126.272,150.997 ; 125.982,151.013 126.287,151.013 ; 125.997,151.028 126.302,151.028 ; 126.013,151.043 126.318,151.043 ; 126.028,151.058 126.333,151.058 ; 126.043,151.074 126.348,151.074 ; 126.058,150.784 125.761,150.784 ; 126.058,151.089 126.363,151.089 ; 126.074,150.799 125.769,150.799 ; 126.074,151.104 126.378,151.104 ; 126.089,151.119 126.396,151.119 ; 126.104,151.134 126.411,151.134 ; 126.119,151.15 126.427,151.15 ; 126.135,151.165 126.442,151.165 ; 126.15,151.18 126.457,151.18 ; 126.165,151.195 126.472,151.195 ; 126.18,151.211 126.488,151.211 ; 126.196,151.226 126.503,151.226 ; 126.211,151.241 126.518,151.241 ; 126.226,151.256 126.533,151.256 ; 126.241,151.272 126.549,151.272 ; 126.259,151.287 126.564,151.287 ; 126.274,151.302 126.579,151.302 ; 126.29,151.317 126.594,151.317 ; 126.305,151.333 126.61,151.333 ; 126.32,151.348 126.625,151.348 ; 126.335,151.363 126.64,151.363 ; 126.351,151.378 126.655,151.378 ; 126.366,151.394 126.671,151.394 ; 126.381,151.409 126.686,151.409 ; 126.396,151.424 126.701,151.424 ; 126.411,151.439 126.716,151.439 ; 126.427,151.455 126.732,151.455 ; 126.442,151.47 126.747,151.47 ; 126.457,151.485 126.762,151.485 ; 126.472,151.5 126.777,151.5 ; 126.488,151.515 126.792,151.515 ; 126.503,151.531 126.808,151.531 ; 126.518,151.546 126.823,151.546 ; 126.533,151.561 126.838,151.561 ; 126.549,151.576 126.853,151.576 ; 126.564,151.592 126.869,151.592 ; 126.579,151.607 126.879,151.607 ; 126.594,151.622 126.886,151.622 ; 126.61,151.637 126.889,151.637 ; 126.625,151.653 126.892,151.653 ; 126.64,151.668 126.889,151.668 ; 126.655,151.683 126.884,151.683 ; 126.671,151.698 126.874,151.698 ; 126.686,151.714 126.864,151.714 ; 126.701,151.729 126.848,151.729 ; 126.716,151.744 126.833,151.744 ; 126.737,151.759 126.81,151.759 ; 125.761,150.784 125.769,150.799 ; 125.761,150.784 125.754,150.751 125.756,150.733 125.761,150.718 125.782,150.687 125.81,150.66 125.84,150.639 125.855,150.634 125.873,150.632 125.906,150.639 125.919,150.647 ; 125.769,150.799 125.779,150.812 126.726,151.754 126.739,151.762 126.772,151.769 126.79,151.767 126.805,151.762 126.836,151.742 126.864,151.714 ; 125.919,150.647 126.866,151.589 126.876,151.602 126.884,151.617 126.892,151.65 126.889,151.668 ; 126.864,151.714 126.884,151.683 ; 126.884,151.683 126.889,151.668
  Top Layer w0.203: 86.508,149.913 87.143,150.548 125.667,150.548 126.323,151.201
  Top Layer w0.635: pad.1@75.967,137.086 75.967,139.372 86.508,149.913
$Net12: pad.1@78.507,137.086 | length 79.1
  Top Layer w0.03: 126.109,150.385 126.366,150.385 ; 126.109,150.4 126.381,150.4 ; 126.112,150.416 126.396,150.416 ; 126.114,150.37 126.351,150.37 ; 126.122,150.355 126.335,150.355 ; 126.132,150.339 126.32,150.339 ; 126.137,150.461 126.442,150.461 ; 126.145,150.324 126.305,150.324 ; 126.152,150.477 126.457,150.477 ; 126.16,150.309 126.29,150.309 ; 126.168,150.492 126.472,150.492 ; 126.183,150.294 126.272,150.294 ; 126.183,150.507 126.488,150.507 ; 126.198,150.522 126.503,150.522 ; 126.213,150.538 126.518,150.538 ; 126.229,150.553 126.533,150.553 ; 126.244,150.568 126.549,150.568 ; 126.259,150.583 126.564,150.583 ; 126.274,150.599 126.579,150.599 ; 126.29,150.614 126.594,150.614 ; 126.305,150.629 126.61,150.629 ; 126.32,150.644 126.625,150.644 ; 126.335,150.66 126.64,150.66 ; 126.351,150.675 126.655,150.675 ; 126.366,150.69 126.671,150.69 ; 126.381,150.705 126.686,150.705 ; 126.396,150.72 126.701,150.72 ; 126.411,150.431 126.114,150.431 ; 126.411,150.736 126.716,150.736 ; 126.427,150.446 126.122,150.446 ; 126.427,150.751 126.732,150.751 ; 126.442,150.766 126.749,150.766 ; 126.457,150.781 126.765,150.781 ; 126.472,150.797 126.78,150.797 ; 126.488,150.812 126.795,150.812 ; 126.503,150.827 126.81,150.827 ; 126.518,150.842 126.826,150.842 ; 126.533,150.858 126.841,150.858 ; 126.549,150.873 126.856,150.873 ; 126.564,150.888 126.871,150.888 ; 126.579,150.903 126.886,150.903 ; 126.594,150.919 126.902,150.919 ; 126.612,150.934 126.917,150.934 ; 126.627,150.949 126.932,150.949 ; 126.643,150.964 126.947,150.964 ; 126.658,150.98 126.963,150.98 ; 126.673,150.995 126.978,150.995 ; 126.688,151.01 126.993,151.01 ; 126.704,151.025 127.008,151.025 ; 126.719,151.041 127.024,151.041 ; 126.734,151.056 127.039,151.056 ; 126.749,151.071 127.054,151.071 ; 126.765,151.086 127.069,151.086 ; 126.78,151.101 127.085,151.101 ; 126.795,151.117 127.1,151.117 ; 126.81,151.132 127.115,151.132 ; 126.826,151.147 127.13,151.147 ; 126.841,151.162 127.146,151.162 ; 126.856,151.178 127.161,151.178 ; 126.871,151.193 127.176,151.193 ; 126.886,151.208 127.191,151.208 ; 126.902,151.223 127.207,151.223 ; 126.917,151.239 127.222,151.239 ; 126.932,151.254 127.232,151.254 ; 126.947,151.269 127.24,151.269 ; 126.963,151.284 127.242,151.284 ; 126.978,151.3 127.245,151.3 ; 126.993,151.315 127.242,151.315 ; 127.008,151.33 127.237,151.33 ; 127.024,151.345 127.227,151.345 ; 127.039,151.361 127.217,151.361 ; 127.054,151.376 127.201,151.376 ; 127.069,151.391 127.186,151.391 ; 127.09,151.406 127.163,151.406 ; 126.114,150.431 126.122,150.446 ; 126.114,150.431 126.107,150.398 126.109,150.38 126.114,150.365 126.135,150.334 126.163,150.306 126.193,150.286 126.208,150.281 126.226,150.279 126.259,150.286 126.272,150.294 ; 126.122,150.446 126.132,150.459 127.08,151.401 127.092,151.409 127.125,151.416 127.143,151.414 127.158,151.409 127.189,151.388 127.217,151.361 ; 126.272,150.294 127.219,151.236 127.229,151.249 127.237,151.264 127.245,151.297 127.242,151.315 ; 127.217,151.361 127.237,151.33 ; 127.237,151.33 127.242,151.315
  Top Layer w0.203: 88.54,149.405 89.175,150.04 125.868,150.04 126.676,150.847
  Top Layer w0.635: pad.1@78.507,137.086 78.507,139.372 88.54,149.405
$Net13: pad.1@81.047,137.086 | length 76.8
  Top Layer w0.03: 126.462,150.032 126.719,150.032 ; 126.462,150.047 126.734,150.047 ; 126.465,150.063 126.749,150.063 ; 126.467,150.017 126.704,150.017 ; 126.475,150.002 126.688,150.002 ; 126.485,149.986 126.673,149.986 ; 126.49,150.108 126.795,150.108 ; 126.498,149.971 126.658,149.971 ; 126.505,150.124 126.81,150.124 ; 126.513,149.956 126.643,149.956 ; 126.521,150.139 126.826,150.139 ; 126.536,149.941 126.625,149.941 ; 126.536,150.154 126.841,150.154 ; 126.551,150.169 126.856,150.169 ; 126.566,150.185 126.871,150.185 ; 126.582,150.2 126.886,150.2 ; 126.597,150.215 126.902,150.215 ; 126.612,150.23 126.917,150.23 ; 126.627,150.245 126.932,150.245 ; 126.643,150.261 126.947,150.261 ; 126.658,150.276 126.963,150.276 ; 126.673,150.291 126.978,150.291 ; 126.688,150.306 126.993,150.306 ; 126.704,150.322 127.008,150.322 ; 126.719,150.337 127.024,150.337 ; 126.734,150.352 127.039,150.352 ; 126.749,150.367 127.054,150.367 ; 126.765,150.078 126.467,150.078 ; 126.765,150.383 127.069,150.383 ; 126.78,150.093 126.475,150.093 ; 126.78,150.398 127.085,150.398 ; 126.795,150.413 127.102,150.413 ; 126.81,150.428 127.118,150.428 ; 126.826,150.444 127.133,150.444 ; 126.841,150.459 127.148,150.459 ; 126.856,150.474 127.163,150.474 ; 126.871,150.489 127.179,150.489 ; 126.886,150.505 127.194,150.505 ; 126.902,150.52 127.209,150.52 ; 126.917,150.535 127.224,150.535 ; 126.932,150.55 127.24,150.55 ; 126.947,150.566 127.255,150.566 ; 126.965,150.581 127.27,150.581 ; 126.98,150.596 127.285,150.596 ; 126.996,150.611 127.3,150.611 ; 127.011,150.626 127.316,150.626 ; 127.026,150.642 127.331,150.642 ; 127.041,150.657 127.346,150.657 ; 127.057,150.672 127.361,150.672 ; 127.072,150.687 127.377,150.687 ; 127.087,150.703 127.392,150.703 ; 127.102,150.718 127.407,150.718 ; 127.118,150.733 127.422,150.733 ; 127.133,150.748 127.438,150.748 ; 127.148,150.764 127.453,150.764 ; 127.163,150.779 127.468,150.779 ; 127.179,150.794 127.483,150.794 ; 127.194,150.809 127.499,150.809 ; 127.209,150.825 127.514,150.825 ; 127.224,150.84 127.529,150.84 ; 127.24,150.855 127.544,150.855 ; 127.255,150.87 127.56,150.87 ; 127.27,150.886 127.575,150.886 ; 127.285,150.901 127.585,150.901 ; 127.3,150.916 127.593,150.916 ; 127.316,150.931 127.595,150.931 ; 127.331,150.947 127.598,150.947 ; 127.346,150.962 127.595,150.962 ; 127.361,150.977 127.59,150.977 ; 127.377,150.992 127.58,150.992 ; 127.392,151.007 127.57,151.007 ; 127.407,151.023 127.554,151.023 ; 127.422,151.038 127.539,151.038 ; 127.443,151.053 127.516,151.053 ; 126.467,150.078 126.475,150.093 ; 126.467,150.078 126.46,150.045 126.462,150.027 126.467,150.012 126.488,149.981 126.516,149.953 126.546,149.933 126.561,149.928 126.579,149.925 126.612,149.933 126.625,149.941 ; 126.475,150.093 126.485,150.106 127.433,151.048 127.445,151.056 127.478,151.063 127.496,151.061 127.511,151.056 127.542,151.035 127.57,151.007 ; 126.625,149.941 127.572,150.883 127.582,150.896 127.59,150.911 127.598,150.944 127.595,150.962 ; 127.57,151.007 127.59,150.977 ; 127.59,150.977 127.595,150.962
  Top Layer w0.203: 90.572,148.897 91.207,149.532 126.066,149.532 127.029,150.494
  Top Layer w0.635: pad.1@81.047,137.086 81.047,139.372 90.572,148.897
